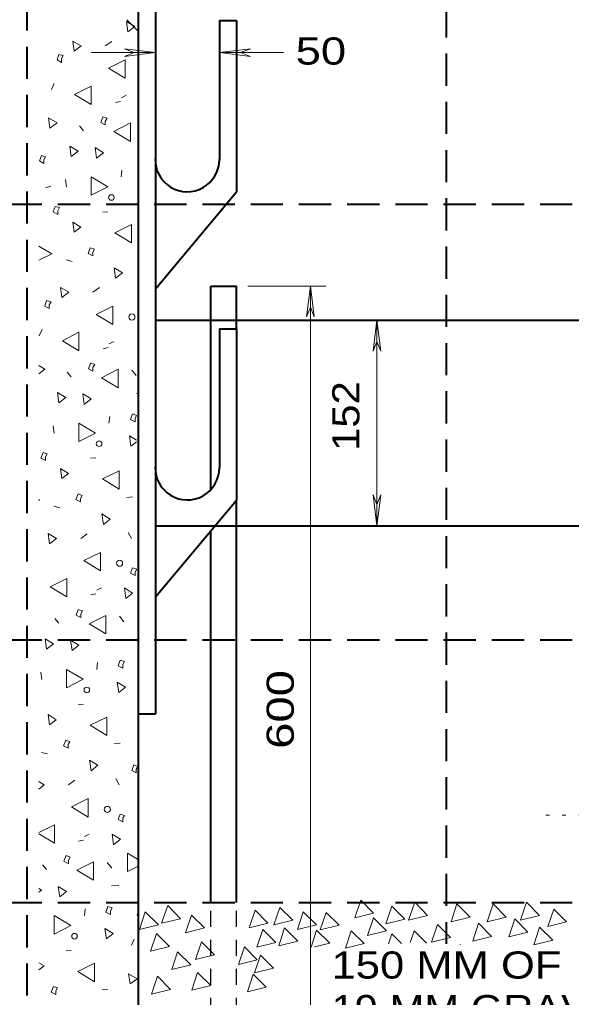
# Model space of a CAD drawing. Extents: x 312583 to 312854, y 144419 to 144597.
# Drawn here: x 312714.43 to 312729.88, y 144432.31 to 144459.67 of the extents above; entities that cross this region are included whole.
import ezdxf

# ---------------------------------------------------------------- set-up
doc = ezdxf.new("R2010")
doc.units = 0
doc.header["$LTSCALE"] = 0.3
for name, pattern in [('DOTTED', [1.5, 0.3, -1.2]), ('MEDIUM_DASHED', [4.5, 3, -1.5]), ('SHORT_DASHED', [2.7, 1.5, -1.2])]:
    doc.linetypes.add(name, pattern=pattern)
doc.layers.add('1', color=7, linetype='Continuous', lineweight=13)

msp = doc.modelspace()

# ---------------------------------------------------------------- linework, layer by layer
at = {"layer": '1', "linetype": 'SHORT_DASHED', "lineweight": 25}
for p, q in [((312717.7513, 144459.3469), (312704.8483, 144472.3419)), ((312719.7906, 144426.9935), (312719.7906, 144434.9669)), ((312720.5036, 144426.9935), (312720.5036, 144434.9669))]:
    msp.add_line(p, q, dxfattribs=at)
at = {"layer": '1', "lineweight": 40}
for p, q in [((312717.7513, 144471.1459), (312717.7513, 144429.2169)), ((312718.2343, 144470.9082), (312718.2343, 144440.2415)), ((312720.0283, 144459.6459), (312720.0283, 144455.7512)), ((312720.0283, 144459.6459), (312720.5036, 144459.6459)), ((312720.5036, 144459.6459), (312720.5036, 144454.8542)), ((312718.2343, 144452.1402), (312720.5036, 144454.8542)), ((312719.7906, 144452.2169), (312720.5036, 144452.2169)), ((312719.7906, 144446.5205), (312719.7906, 144452.2169)), ((312720.5036, 144451.0209), (312720.5036, 144452.2169)), ((312718.2343, 144451.2585), (312734.5259, 144451.2585)), ((312720.0283, 144451.0209), (312720.0283, 144447.1262)), ((312720.0283, 144451.0209), (312720.5036, 144451.0209)), ((312720.5036, 144451.0209), (312720.5036, 144446.2292)), ((312718.2343, 144443.5152), (312720.5036, 144446.2292)), ((312720.5036, 144434.9669), (312720.5036, 144446.2292)), ((312718.2343, 144445.5085), (312734.5259, 144445.5085)), ((312719.7906, 144434.9669), (312719.7906, 144445.3705)), ((312717.7513, 144440.2415), (312718.2343, 144440.2415))]:
    msp.add_line(p, q, dxfattribs=at)
at = {"layer": '1', "linetype": 'MEDIUM_DASHED', "lineweight": 40}
for p, q in [((312714.6386, 144469.7122), (312714.6386, 144432.0919)), ((312726.3763, 144468.1712), (312726.3763, 144433.8092)), ((312699.3053, 144454.5092), (312738.8346, 144454.5092)), ((312699.3053, 144442.3192), (312738.8346, 144442.3192)), ((312699.3053, 144434.9669), (312738.8346, 144434.9669))]:
    msp.add_line(p, q, dxfattribs=at)
at = {"layer": '1'}
for p, q in [((312714.9683, 144459.3852), (312714.9759, 144459.3852)), ((312717.0153, 144459.0632), (312716.8313, 144458.9329)), ((312716.4326, 144458.7489), (312718.2343, 144458.7489)), ((312717.3679, 144458.8562), (312717.6439, 144458.7489)), ((312718.2343, 144458.7489), (312717.3679, 144458.8562)), ((312717.3679, 144458.6415), (312717.6439, 144458.7489)), ((312718.2343, 144458.7489), (312717.3679, 144458.6415)), ((312720.0283, 144458.7489), (312720.8946, 144458.8562)), ((312720.0283, 144458.7489), (312720.8946, 144458.6415)), ((312720.0283, 144458.7489), (312721.8223, 144458.7489)), ((312720.8946, 144458.8562), (312720.6186, 144458.7489)), ((312720.8946, 144458.6415), (312720.6186, 144458.7489)), ((312715.4053, 144457.8825), (312715.3286, 144457.7139)), ((312717.1149, 144457.3535), (312717.2606, 144457.3842)), ((312717.2836, 144457.4839), (312717.4139, 144457.5605)), ((312716.1106, 144456.7019), (312716.2179, 144456.5562)), ((312717.2759, 144455.2759), (312717.2989, 144455.4599)), ((312715.7196, 144455.1992), (312715.7426, 144454.9845)), ((312715.1599, 144454.9615), (312715.3056, 144455.0075)), ((312716.7623, 144454.2869), (312716.9079, 144454.2945)), ((312715.7349, 144452.9452), (312715.9036, 144452.9069)), ((312716.6703, 144452.1785), (312716.4863, 144452.0405)), ((312720.8256, 144452.2169), (312723.0029, 144452.2169)), ((312722.5736, 144452.2169), (312722.4663, 144451.3505)), ((312722.5736, 144452.2169), (312722.5736, 144429.2169)), ((312722.5736, 144452.2169), (312722.6809, 144451.3505)), ((312722.4663, 144451.3505), (312722.5736, 144451.6265)), ((312722.6809, 144451.3505), (312722.5736, 144451.6265)), ((312724.4366, 144451.2585), (312724.3293, 144450.3922)), ((312724.4366, 144451.2585), (312724.4366, 144445.5085)), ((312724.4366, 144451.2585), (312724.5439, 144450.3922)), ((312715.0603, 144450.9979), (312714.9836, 144450.8215)), ((312716.9386, 144450.5992), (312717.0689, 144450.6682)), ((312724.3293, 144450.3922), (312724.4366, 144450.6682)), ((312724.5439, 144450.3922), (312724.4366, 144450.6682)), ((312716.7699, 144450.4612), (312716.9156, 144450.4919)), ((312715.7656, 144449.8095), (312715.8729, 144449.6715)), ((312717.5749, 144449.8632), (312717.6976, 144449.7099)), ((312717.6976, 144449.2115), (312717.7053, 144449.2115)), ((312717.6669, 144448.5139), (312717.7053, 144448.5905)), ((312716.9309, 144448.3835), (312716.9616, 144448.5675)), ((312715.3746, 144448.3069), (312715.3976, 144448.0999)), ((312717.5443, 144447.7319), (312717.7053, 144447.8545)), ((312716.4173, 144447.4022), (312716.5629, 144447.4099)), ((312717.4369, 144446.2982), (312717.5903, 144446.3135)), ((312724.3293, 144446.3749), (312724.4366, 144446.0989)), ((312724.4366, 144445.5085), (312724.3293, 144446.3749)), ((312724.5439, 144446.3749), (312724.4366, 144446.0989)), ((312724.4366, 144445.5085), (312724.5439, 144446.3749)), ((312715.3899, 144446.0605), (312715.5586, 144446.0145)), ((312717.4753, 144445.3245), (312717.5673, 144445.1559)), ((312716.3253, 144445.2862), (312716.1489, 144445.1482)), ((312716.5936, 144443.7069), (312716.7239, 144443.7759)), ((312716.4249, 144443.5765), (312716.5706, 144443.5995)), ((312715.4206, 144442.9172), (312715.5279, 144442.7792)), ((312717.2299, 144442.9785), (312717.3526, 144442.8175)), ((312717.3526, 144442.3192), (312717.5596, 144442.3345)), ((312716.5936, 144441.4912), (312716.6166, 144441.6829)), ((312715.0296, 144441.4145), (312715.0526, 144441.2075)), ((312716.0723, 144440.5099), (312716.2179, 144440.5175)), ((312717.0919, 144439.4135), (312717.2453, 144439.4212)), ((312715.0449, 144439.1682), (312715.2136, 144439.1222)), ((312717.6976, 144438.7005), (312717.7283, 144438.7465)), ((312715.9803, 144438.3939), (312715.8039, 144438.2635)), ((312717.1303, 144438.4322), (312717.2223, 144438.2635)), ((312714.9683, 144436.8912), (312715.4129, 144436.6229)), ((312716.2486, 144436.8145), (312716.3789, 144436.8835)), ((312716.0799, 144436.6842), (312716.2256, 144436.7149)), ((312717.7359, 144436.1782), (312717.4523, 144436.3469)), ((312715.0756, 144436.0249), (312715.1829, 144435.8869)), ((312716.8849, 144436.0862), (312717.0153, 144435.9252)), ((312717.0076, 144435.4345), (312717.2146, 144435.4422)), ((312716.2486, 144434.5989), (312716.2716, 144434.7905)), ((312717.6439, 144433.9395), (312717.5673, 144433.7709)), ((312722.6886, 144433.7249), (312723.1179, 144433.8322)), ((312715.7349, 144433.6175), (312715.8806, 144433.6252)), ((312716.7469, 144432.5212), (312716.9003, 144432.5289))]:
    msp.add_line(p, q, dxfattribs=at)
at = {"layer": '1', "linetype": 'DOTTED'}
msp.add_line((312729.1669, 144437.4125), (312744.8913, 144437.4125), dxfattribs=at)
at = {"layer": '1'}
for points in [[(312717.4676, 144459.3315), (312717.6593, 144459.4772), (312717.4216, 144459.6152)], [(312715.9649, 144458.7872), (312716.1566, 144458.9329), (312715.9189, 144459.0709)], [(312715.6046, 144458.5802), (312715.6506, 144458.6645), (312715.5356, 144458.6952), (312715.4819, 144458.5495), (312715.6046, 144458.4729)], [(312717.3909, 144458.0282), (312717.3909, 144458.5495), (312716.9233, 144458.3119)], [(312716.4403, 144457.2922), (312716.4403, 144457.8135), (312715.9726, 144457.5759)], [(312715.2826, 144456.6329), (312715.4819, 144456.7785), (312715.2443, 144456.9242)], [(312716.8313, 144456.8245), (312716.8849, 144456.9089), (312716.7623, 144456.9472), (312716.7086, 144456.7939), (312716.8313, 144456.7249)], [(312717.5366, 144456.2572), (312717.5366, 144456.7785), (312717.0689, 144456.5409)], [(312715.8806, 144455.8432), (312716.0723, 144455.9889), (312715.8423, 144456.1269)], [(312716.5859, 144455.7972), (312716.7853, 144455.9429), (312716.5476, 144456.0885)], [(312715.1139, 144455.7512), (312715.1599, 144455.8355), (312715.0449, 144455.8662), (312714.9913, 144455.7205), (312715.1139, 144455.6439)], [(312716.4326, 144455.2759), (312716.4326, 144454.7622), (312716.9003, 144454.9922)], [(312715.5049, 144454.3252), (312715.5509, 144454.4095), (312715.4283, 144454.4402), (312715.3746, 144454.2945), (312715.5049, 144454.2179)], [(312715.9573, 144453.7195), (312716.1489, 144453.8652), (312715.9189, 144454.0032)], [(312717.5673, 144453.4282), (312717.5673, 144453.9419), (312717.0996, 144453.7042)], [(312716.4863, 144453.1675), (312716.5323, 144453.2519), (312716.4096, 144453.2825), (312716.3559, 144453.1292), (312716.4863, 144453.0602)], [(312717.1226, 144452.4392), (312717.3143, 144452.5849), (312717.0766, 144452.7229)], [(312715.6199, 144451.8949), (312715.8116, 144452.0405), (312715.5816, 144452.1785)], [(312715.2596, 144451.6879), (312715.3133, 144451.7722), (312715.1906, 144451.8105), (312715.1369, 144451.6572), (312715.2596, 144451.5882)], [(312717.0459, 144451.1435), (312717.0459, 144451.6572), (312716.5783, 144451.4195)], [(312716.0953, 144450.4075), (312716.0953, 144450.9212), (312715.6353, 144450.6835)], [(312716.4863, 144449.9399), (312716.5399, 144450.0165), (312716.4173, 144450.0549), (312716.3636, 144449.9015), (312716.4863, 144449.8325)], [(312717.1916, 144449.3725), (312717.1916, 144449.8862), (312716.7239, 144449.6485)], [(312715.5356, 144448.9509), (312715.7273, 144449.0965), (312715.4973, 144449.2345)], [(312716.2409, 144448.9049), (312716.4403, 144449.0582), (312716.2026, 144449.1962)], [(312716.0876, 144448.3835), (312716.0876, 144447.8699), (312716.5553, 144448.0999)], [(312715.1599, 144447.4329), (312715.2059, 144447.5172), (312715.0909, 144447.5555), (312715.0296, 144447.4022), (312715.1599, 144447.3332)], [(312715.6123, 144446.8272), (312715.8039, 144446.9729), (312715.5739, 144447.1109)], [(312717.2223, 144446.5359), (312717.2223, 144447.0495), (312716.7546, 144446.8195)], [(312716.1413, 144446.2752), (312716.1873, 144446.3595), (312716.0723, 144446.3979), (312716.0109, 144446.2445), (312716.1413, 144446.1755)], [(312716.7776, 144445.5469), (312716.9693, 144445.6925), (312716.7393, 144445.8382)], [(312715.2749, 144445.0025), (312715.4666, 144445.1482), (312715.2366, 144445.2939)], [(312716.7009, 144444.2512), (312716.7009, 144444.7649), (312716.2333, 144444.5349)], [(312717.6669, 144444.2129), (312717.7129, 144444.2972), (312717.5979, 144444.3355), (312717.5366, 144444.1822), (312717.6669, 144444.1132)], [(312715.7579, 144443.5152), (312715.7579, 144444.0289), (312715.2903, 144443.7989)], [(312717.4063, 144443.4769), (312717.5979, 144443.6225), (312717.3679, 144443.7682)], [(312716.1489, 144443.0475), (312716.1949, 144443.1319), (312716.0723, 144443.1625), (312716.0186, 144443.0092), (312716.1489, 144442.9402)], [(312716.8466, 144442.4802), (312716.8466, 144442.9939), (312716.3789, 144442.7639)], [(312715.1906, 144442.0585), (312715.3823, 144442.2042), (312715.1523, 144442.3422)], [(312715.9036, 144442.0202), (312716.0953, 144442.1659), (312715.8576, 144442.3039)], [(312717.3219, 144441.6292), (312717.3679, 144441.7059), (312717.2529, 144441.7442), (312717.1916, 144441.5909), (312717.3219, 144441.5219)], [(312715.7426, 144441.4912), (312715.7426, 144440.9775), (312716.2103, 144441.2152)], [(312717.2069, 144440.8395), (312717.3986, 144440.9929), (312717.1609, 144441.1309)], [(312715.2673, 144439.9349), (312715.4589, 144440.0805), (312715.2289, 144440.2262)], [(312716.8773, 144439.6435), (312716.8773, 144440.1572), (312716.4096, 144439.9272)], [(312715.7963, 144439.3905), (312715.8423, 144439.4672), (312715.7273, 144439.5055), (312715.6659, 144439.3522), (312715.7963, 144439.2832)], [(312716.4326, 144438.6545), (312716.6243, 144438.8079), (312716.3943, 144438.9459)], [(312716.3559, 144437.3589), (312716.3559, 144437.8725), (312715.8883, 144437.6425)], [(312717.3219, 144437.3282), (312717.3679, 144437.4049), (312717.2529, 144437.4432), (312717.1916, 144437.2899), (312717.3219, 144437.2209)], [(312717.0613, 144436.5845), (312717.2606, 144436.7379), (312717.0229, 144436.8759)], [(312715.8039, 144436.1552), (312715.8499, 144436.2395), (312715.7349, 144436.2779), (312715.6736, 144436.1245), (312715.8039, 144436.0479)], [(312716.5016, 144435.5879), (312716.5016, 144436.1015), (312716.0339, 144435.8715)], [(312715.5586, 144435.1279), (312715.7503, 144435.2735), (312715.5126, 144435.4115)], [(312724.3446, 144434.6679), (312723.9843, 144435.0359), (312723.8156, 144434.5375)], [(312725.8549, 144434.6065), (312725.4946, 144434.9745), (312725.3259, 144434.4762)], [(312727.0433, 144434.5605), (312726.6753, 144434.9285), (312726.5143, 144434.4302)], [(312728.0553, 144434.5605), (312727.6873, 144434.9285), (312727.5263, 144434.4302)], [(312728.9906, 144434.6065), (312728.6226, 144434.9745), (312728.4616, 144434.4762)], [(312716.9769, 144434.7369), (312717.0229, 144434.8212), (312716.9079, 144434.8519), (312716.8466, 144434.6985), (312716.9769, 144434.6295)], [(312718.3186, 144434.3459), (312717.9506, 144434.7062), (312717.7896, 144434.2155)], [(312718.9396, 144434.5145), (312718.5793, 144434.8825), (312718.4106, 144434.3842)], [(312721.3853, 144434.3919), (312721.0249, 144434.7522), (312720.8563, 144434.2615)], [(312722.0829, 144434.4685), (312721.7226, 144434.8289), (312721.5539, 144434.3382)], [(312722.7423, 144434.3459), (312722.3743, 144434.7062), (312722.2133, 144434.2155)], [(312723.3786, 144434.3305), (312723.0183, 144434.6909), (312722.8496, 144434.2002)], [(312725.2186, 144434.4992), (312724.8506, 144434.8672), (312724.6896, 144434.3689)], [(312729.7496, 144434.4225), (312729.3893, 144434.7829), (312729.2206, 144434.2922)], [(312715.3976, 144434.6065), (312715.3976, 144434.0852), (312715.8653, 144434.3229)], [(312719.6066, 144434.2539), (312719.2463, 144434.6142), (312719.0776, 144434.1159)], [(312724.7049, 144434.1695), (312724.3369, 144434.5375), (312724.1759, 144434.0392)], [(312726.4989, 144433.9855), (312726.1309, 144434.3535), (312725.9699, 144433.8552)], [(312727.6489, 144434.0162), (312727.2809, 144434.3842), (312727.1199, 144433.8859)], [(312728.6609, 144434.1389), (312728.3006, 144434.5069), (312728.1319, 144434.0085)], [(312716.8619, 144433.9549), (312717.0536, 144434.1005), (312716.8159, 144434.2385)], [(312718.6253, 144433.7402), (312718.2649, 144434.1005), (312718.0963, 144433.6022)], [(312721.6076, 144433.8475), (312721.2396, 144434.2079), (312721.0786, 144433.7172)], [(312722.2209, 144433.8859), (312721.8529, 144434.2539), (312721.6919, 144433.7555)], [(312724.0839, 144433.8169), (312723.7159, 144434.1772), (312723.5549, 144433.6865)], [(312729.3586, 144433.9089), (312728.9906, 144434.2769), (312728.8296, 144433.7785)], [(312719.8903, 144433.5025), (312719.5223, 144433.8705), (312719.3613, 144433.3722)], [(312719.2233, 144433.2189), (312718.8553, 144433.5869), (312718.6943, 144433.0885)], [(312721.0863, 144433.3645), (312720.7259, 144433.7249), (312720.5573, 144433.2342)], [(312716.5323, 144432.7512), (312716.5323, 144433.2725), (312716.0646, 144433.0349)], [(312721.5386, 144433.1269), (312721.1783, 144433.4949), (312721.0096, 144432.9965)], [(312719.7829, 144432.6439), (312719.4149, 144433.0119), (312719.2539, 144432.5135)], [(312717.5289, 144432.6899), (312717.7206, 144432.8355), (312717.4829, 144432.9735)], [(312718.6559, 144432.5365), (312718.2956, 144432.9045), (312718.1269, 144432.4062)], [(312721.3393, 144432.5979), (312720.9713, 144432.9659), (312720.8103, 144432.4675)], [(312715.4513, 144432.4982), (312715.4973, 144432.5825), (312715.3823, 144432.6132), (312715.3209, 144432.4599), (312715.4513, 144432.3909)]]:
    msp.add_lwpolyline(points, close=True, dxfattribs=at)
for points in [[(312714.9683, 144452.9375), (312715.3363, 144453.1215), (312714.9683, 144453.3362)], [(312714.9683, 144449.7635), (312715.1369, 144449.8939), (312714.9683, 144449.9935)], [(312717.7053, 144448.5982), (312717.5979, 144448.6365), (312717.5366, 144448.4832), (312717.6669, 144448.4142), (312717.6669, 144448.5139)], [(312717.7053, 144447.9005), (312717.5059, 144448.0232), (312717.5443, 144447.7319)], [(312714.9683, 144446.2139), (312714.9913, 144446.2292), (312714.9683, 144446.2445)], [(312717.7283, 144438.7849), (312717.6286, 144438.8155), (312717.5749, 144438.6622), (312717.6976, 144438.5932), (312717.6976, 144438.7005)], [(312714.9683, 144438.1409), (312715.1216, 144438.2635), (312714.9683, 144438.3555)], [(312715.4129, 144436.6229), (312715.4129, 144437.1365), (312714.9683, 144436.9219)], [(312717.4523, 144436.3469), (312717.4523, 144435.8332), (312717.7359, 144435.9712)], [(312714.9683, 144435.2582), (312715.0449, 144435.3119), (312714.9683, 144435.3579)], [(312717.7359, 144434.6602), (312717.7206, 144434.5989), (312717.7436, 144434.5912)], [(312723.1179, 144433.8322), (312722.7499, 144434.1925), (312722.5966, 144433.7172)], [(312725.1266, 144433.8169), (312724.8583, 144434.0929), (312724.7586, 144433.8092)], [(312725.8243, 144433.8322), (312725.4793, 144434.1772), (312725.3643, 144433.8475)], [(312726.7749, 144433.7939), (312726.7673, 144433.8015), (312726.7673, 144433.7939)], [(312714.9683, 144433.0809), (312715.1216, 144433.1959), (312714.9683, 144433.2802)]]:
    msp.add_lwpolyline(points, dxfattribs=at)
for centre, radius in [((312717.0034, 144454.6945), 0.0784), ((312717.5762, 144451.3512), 0.0865), ((312716.6591, 144447.8042), 0.0784), ((312717.232, 144444.461), 0.0865), ((312716.3149, 144440.9139), 0.0784), ((312716.8877, 144437.5707), 0.0865), ((312715.9706, 144434.0236), 0.0784)]:
    msp.add_circle(centre, radius, dxfattribs=at)
at = {"layer": '1', "lineweight": 40}
for centre in [(312719.1284, 144455.7546), (312719.1284, 144447.1296)]:
    msp.add_arc(centre, 0.8984, 178.12864, 359.96943, dxfattribs=at)

# ---------------------------------------------------------------- texts
at = {"layer": '1'}
for s, width, p in [('50 ', 1.25, (312722.1626, 144458.4124)), ('150 MM OF', 1.2, (312723.1664, 144432.8376)), ('19 MM GRAVEL OR', 1.15, (312723.1664, 144431.6176))]:
    msp.add_text(s, height=0.76, dxfattribs=dict(at, width=width)).set_placement(p)
for s, width, p in [('152 ', 1.15, (312723.9475, 144447.6024)), ('600 ', 1.3, (312722.1098, 144439.2663))]:
    msp.add_text(s, height=0.76, rotation=90, dxfattribs=dict(at, width=width)).set_placement(p)

doc.saveas('drawing.dxf')
